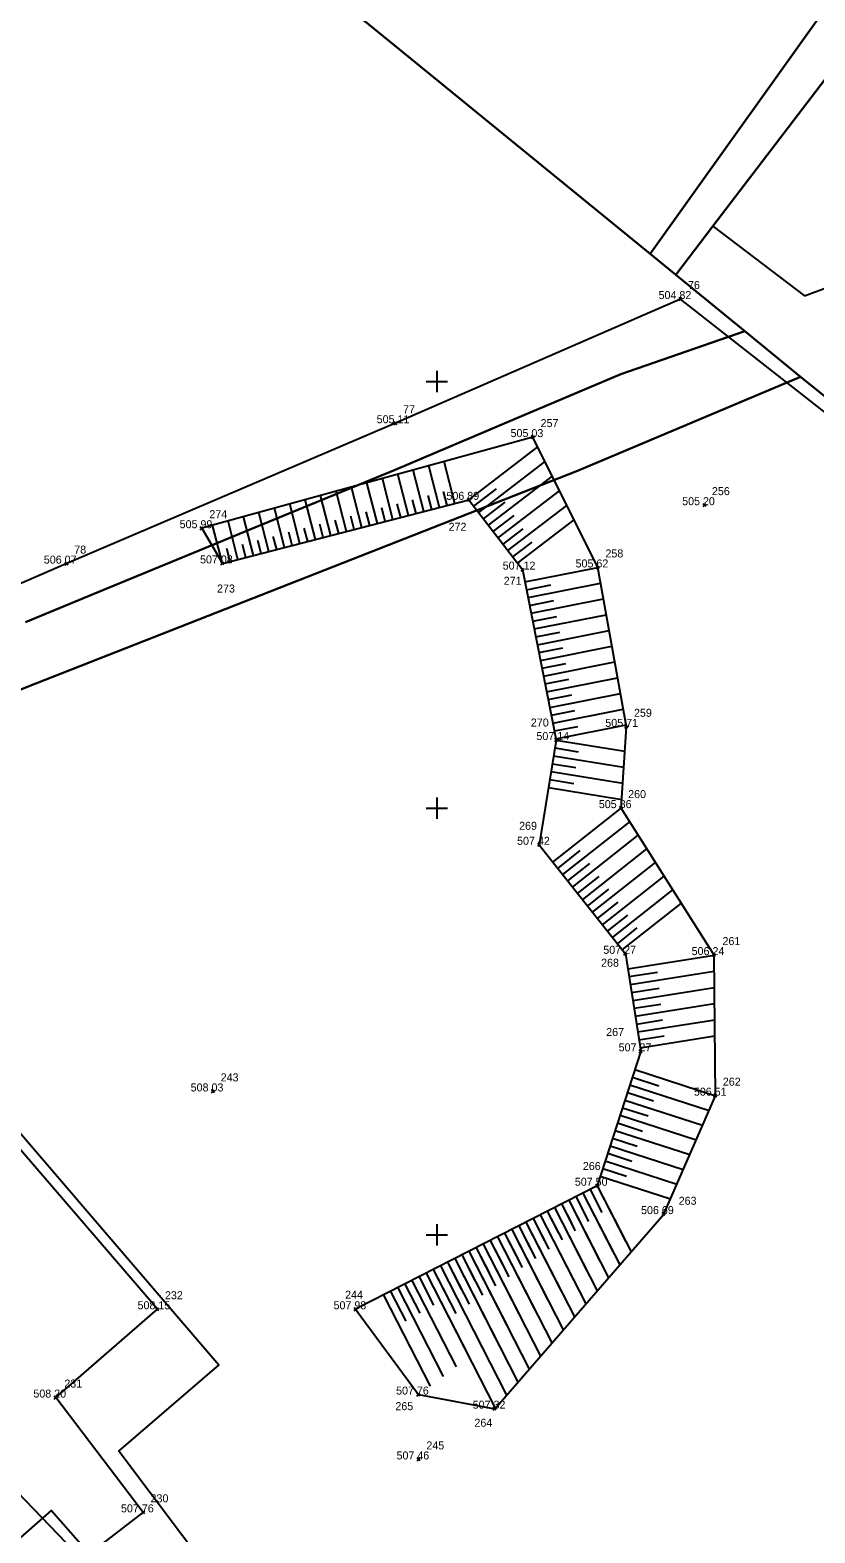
# Model space of a CAD drawing. Extents: x -408550 to -407654, y -1233019 to -1231230.
# Drawn here: x -408039.1 to -408002.3, y -1232014 to -1231943.5 of the extents above; entities that cross this region are included whole.
import ezdxf

# ---------------------------------------------------------------- set-up
doc = ezdxf.new("R2010")
doc.units = 0
for name, color, linetype in [('Level 1', 7, 'Continuous'), ('Level 12', 7, 'Continuous'), ('Level 13', 7, 'Continuous'), ('Level 16', 7, 'Continuous'), ('Level 23', 7, 'Continuous'), ('Level 26', 7, 'Continuous'), ('Level 4', 7, 'Continuous'), ('Level 40', 7, 'Continuous'), ('Level 5', 7, 'Continuous')]:
    doc.layers.add(name, color=color, linetype=linetype)

msp = doc.modelspace()

# ---------------------------------------------------------------- linework, layer by layer
at = {"layer": 'Level 1'}
for p, q in [((-408020, -1231959.5), (-408020, -1231960.5)), ((-408020.5, -1231960), (-408019.5, -1231960)), ((-408020, -1231979.5), (-408020, -1231980.5)), ((-408020.5, -1231980), (-408019.5, -1231980)), ((-408020, -1231999.5), (-408020, -1232000.5)), ((-408020.5, -1232000), (-408019.5, -1232000))]:
    msp.add_line(p, q, dxfattribs=at)
for points in [[(-407991.04, -1231886.54), (-407990.51, -1231886.91), (-407979.53, -1231894.66), (-407981.86, -1231897.95), (-407972.2, -1231905.71), (-407991.32, -1231932.1), (-408007.06, -1231952.72), (-408008.8, -1231955), (-408010, -1231954.02), (-407982.21, -1231915.1), (-407987.32, -1231909.48), (-407982.96, -1231899.31), (-407994.22, -1231890.85)], [(-408000.99, -1231900.39), (-407998.47, -1231896.8), (-407995.49, -1231892.56), (-407994.22, -1231890.85), (-407982.96, -1231899.31), (-407987.32, -1231909.48), (-407982.21, -1231915.1), (-408010, -1231954.02), (-408021.76, -1231944.43), (-408028.78, -1231938.7)], [(-407991.32, -1231932.1), (-407979.12, -1231940.92), (-407973.26, -1231945.16), (-407968, -1231948.96), (-407967.25, -1231949.5), (-407985.37, -1231974.5), (-407998.58, -1231963.3), (-408002.95, -1231959.78), (-408005.56, -1231957.64), (-408008.8, -1231955), (-408007.06, -1231952.72)]]:
    msp.add_lwpolyline(points, close=True, dxfattribs=at)
for points in [[(-408044.57, -1231925.63), (-408028.78, -1231938.7), (-408021.76, -1231944.43), (-408010, -1231954.02), (-408008.8, -1231955), (-408005.56, -1231957.64), (-408011.38, -1231959.66), (-408016.43, -1231961.8), (-408021.95, -1231964.14), (-408028.53, -1231966.85), (-408031.4, -1231968.04), (-408035.38, -1231969.67), (-408039.27, -1231971.28)], [(-408039.27, -1231971.28), (-408035.38, -1231969.67), (-408031.4, -1231968.04), (-408028.53, -1231966.85), (-408021.95, -1231964.14), (-408016.43, -1231961.8), (-408011.38, -1231959.66), (-408005.56, -1231957.64), (-408002.95, -1231959.78), (-408013.4, -1231964.19), (-408038.79, -1231974.16), (-408066.68, -1231985.23)], [(-408066.68, -1231985.23), (-408038.79, -1231974.16), (-408013.4, -1231964.19), (-408002.95, -1231959.78)], [(-408002.95, -1231959.78), (-407998.58, -1231963.3), (-407985.37, -1231974.5), (-407975.08, -1231982.73), (-407972.21, -1231984.54), (-407969.45, -1231986.76), (-407966.11, -1231989.44), (-407955.64, -1231997.88), (-407939.09, -1232011.47), (-407927.08, -1232021.88), (-407908.02, -1232037.31)]]:
    msp.add_lwpolyline(points, dxfattribs=at)
at = {"layer": 'Level 12'}
msp.add_lwpolyline([(-407921.23, -1232026.55), (-407939.09, -1232011.64), (-407955.83, -1231997.88), (-407968.95, -1231986.9), (-407969.06, -1231986.9), (-407974.7, -1231982.55), (-407975.01, -1231982.78), (-407988.1, -1231972.38), (-407997.03, -1231965.19), (-408008.57, -1231956.14), (-408021.93, -1231961.96), (-408037.34, -1231968.54), (-408046.88, -1231972.68)], dxfattribs=at)
at = {"layer": 'Level 13'}
for p, q in [((-408018.49, -1231965.55), (-408015.261, -1231963.071)), ((-408019.147, -1231965.719), (-408019.653, -1231963.755)), ((-408018.033, -1231966.145), (-408014.92, -1231963.755)), ((-408021.325, -1231966.282), (-408021.823, -1231964.352)), ((-408020.599, -1231966.094), (-408021.1, -1231964.153)), ((-408019.873, -1231965.907), (-408020.377, -1231963.954)), ((-408017.577, -1231966.74), (-408014.58, -1231964.439)), ((-408024.23, -1231967.031), (-408024.716, -1231965.148)), ((-408023.504, -1231966.844), (-408023.993, -1231964.949)), ((-408022.778, -1231966.656), (-408023.27, -1231964.75)), ((-408022.052, -1231966.469), (-408022.546, -1231964.551)), ((-408019.51, -1231965.813), (-408019.678, -1231965.161)), ((-408018.262, -1231965.847), (-408017.206, -1231965.037)), ((-408017.12, -1231967.335), (-408014.239, -1231965.124)), ((-408026.409, -1231967.593), (-408026.886, -1231965.745)), ((-408025.683, -1231967.406), (-408026.162, -1231965.546)), ((-408024.956, -1231967.218), (-408025.439, -1231965.347)), ((-408021.688, -1231966.375), (-408021.854, -1231965.735)), ((-408020.962, -1231966.188), (-408021.129, -1231965.544)), ((-408020.236, -1231966), (-408020.403, -1231965.352)), ((-408017.805, -1231966.442), (-408016.788, -1231965.662)), ((-408016.663, -1231967.93), (-408013.899, -1231965.808)), ((-408029.314, -1231968.343), (-408029.779, -1231966.541)), ((-408028.588, -1231968.155), (-408029.055, -1231966.342)), ((-408027.861, -1231967.968), (-408028.332, -1231966.143)), ((-408027.135, -1231967.781), (-408027.609, -1231965.944)), ((-408024.593, -1231967.125), (-408024.755, -1231966.5)), ((-408023.867, -1231966.937), (-408024.029, -1231966.308)), ((-408023.141, -1231966.75), (-408023.304, -1231966.117)), ((-408022.415, -1231966.563), (-408022.579, -1231965.926)), ((-408017.348, -1231967.037), (-408016.37, -1231966.286)), ((-408016.207, -1231968.525), (-408013.559, -1231966.492)), ((-408030.04, -1231968.53), (-408030.502, -1231966.74)), ((-408027.498, -1231967.874), (-408027.656, -1231967.265)), ((-408026.772, -1231967.687), (-408026.93, -1231967.073)), ((-408026.046, -1231967.499), (-408026.205, -1231966.882)), ((-408025.32, -1231967.312), (-408025.48, -1231966.691)), ((-408016.892, -1231967.632), (-408015.952, -1231966.911)), ((-408029.677, -1231968.436), (-408029.831, -1231967.838)), ((-408028.951, -1231968.249), (-408029.106, -1231967.647)), ((-408028.224, -1231968.062), (-408028.381, -1231967.456)), ((-408016.435, -1231968.227), (-408015.534, -1231967.535)), ((-408015.866, -1231969.396), (-408012.45, -1231968.72)), ((-408015.793, -1231969.763), (-408014.658, -1231969.539)), ((-408015.721, -1231970.131), (-408012.318, -1231969.458)), ((-408015.648, -1231970.499), (-408014.517, -1231970.276)), ((-408015.575, -1231970.867), (-408012.185, -1231970.197)), ((-408015.502, -1231971.235), (-408014.376, -1231971.012)), ((-408015.43, -1231971.603), (-408012.053, -1231970.935)), ((-408015.357, -1231971.971), (-408014.235, -1231971.749)), ((-408015.284, -1231972.339), (-408011.92, -1231971.673)), ((-408015.211, -1231972.706), (-408014.093, -1231972.485)), ((-408015.139, -1231973.074), (-408011.788, -1231972.412)), ((-408015.066, -1231973.442), (-408013.952, -1231973.222)), ((-408014.993, -1231973.81), (-408011.655, -1231973.15)), ((-408014.92, -1231974.178), (-408013.811, -1231973.959)), ((-408014.848, -1231974.546), (-408011.523, -1231973.888)), ((-408014.775, -1231974.914), (-408013.67, -1231974.695)), ((-408014.702, -1231975.282), (-408011.39, -1231974.627)), ((-408014.629, -1231975.649), (-408013.529, -1231975.432)), ((-408014.557, -1231976.017), (-408011.258, -1231975.365)), ((-408014.484, -1231976.385), (-408013.388, -1231976.168)), ((-408014.411, -1231976.753), (-408011.126, -1231976.103)), ((-408014.4, -1231976.81), (-408011.185, -1231977.334)), ((-408014.521, -1231977.55), (-408011.234, -1231978.086)), ((-408014.46, -1231977.18), (-408013.378, -1231977.356)), ((-408014.641, -1231978.29), (-408011.284, -1231978.838)), ((-408014.581, -1231977.92), (-408013.475, -1231978.101)), ((-408014.762, -1231979.031), (-408011.333, -1231979.589)), ((-408014.702, -1231978.661), (-408013.572, -1231978.845)), ((-408014.56, -1231982.53), (-408011.36, -1231980)), ((-408014.095, -1231983.118), (-408010.957, -1231980.637)), ((-408013.63, -1231983.706), (-408010.553, -1231981.275)), ((-408014.327, -1231982.824), (-408013.272, -1231981.99)), ((-408013.164, -1231984.295), (-408010.15, -1231981.912)), ((-408013.862, -1231983.412), (-408012.827, -1231982.594)), ((-408012.699, -1231984.883), (-408009.747, -1231982.549)), ((-408013.397, -1231984.001), (-408012.383, -1231983.199)), ((-408012.234, -1231985.471), (-408009.344, -1231983.186)), ((-408012.932, -1231984.589), (-408011.938, -1231983.804)), ((-408011.769, -1231986.06), (-408008.94, -1231983.824)), ((-408012.467, -1231985.177), (-408011.494, -1231984.408)), ((-408011.304, -1231986.648), (-408008.537, -1231984.461)), ((-408012.001, -1231985.766), (-408011.049, -1231985.013)), ((-408011.536, -1231986.354), (-408010.605, -1231985.617)), ((-408011.05, -1231987.528), (-408007, -1231986.89)), ((-408010.992, -1231987.899), (-408009.661, -1231987.689)), ((-408010.933, -1231988.269), (-408006.993, -1231987.648)), ((-408010.817, -1231989.01), (-408006.986, -1231988.406)), ((-408010.875, -1231988.639), (-408009.581, -1231988.436)), ((-408010.758, -1231989.38), (-408009.501, -1231989.182)), ((-408010.7, -1231989.751), (-408006.979, -1231989.164)), ((-408010.641, -1231990.121), (-408009.421, -1231989.929)), ((-408010.583, -1231990.492), (-408006.972, -1231989.923)), ((-408010.525, -1231990.862), (-408009.341, -1231990.675)), ((-408010.466, -1231991.232), (-408006.965, -1231990.681)), ((-408010.833, -1231992.614), (-408009.587, -1231993.017)), ((-408010.717, -1231992.257), (-408006.94, -1231993.48)), ((-408011.064, -1231993.327), (-408009.841, -1231993.723)), ((-408010.948, -1231992.97), (-408007.241, -1231994.171)), ((-408011.295, -1231994.041), (-408010.096, -1231994.429)), ((-408011.18, -1231993.684), (-408007.542, -1231994.862)), ((-408011.526, -1231994.754), (-408010.35, -1231995.135)), ((-408011.411, -1231994.397), (-408007.844, -1231995.552)), ((-408011.757, -1231995.468), (-408010.604, -1231995.841)), ((-408011.642, -1231995.111), (-408008.145, -1231996.243)), ((-408011.988, -1231996.181), (-408010.859, -1231996.547)), ((-408011.873, -1231995.824), (-408008.446, -1231996.934)), ((-408012.104, -1231996.538), (-408008.747, -1231997.625)), ((-408012.335, -1231997.252), (-408009.049, -1231998.316)), ((-408012.219, -1231996.895), (-408011.113, -1231997.253)), ((-408013.482, -1231998.212), (-408012.885, -1231999.378)), ((-408013.482, -1231998.212), (-408013.005, -1231999.144)), ((-408013.148, -1231998.042), (-408011.426, -1232001.409)), ((-408013.148, -1231998.042), (-408011.745, -1232000.784)), ((-408012.814, -1231997.871), (-408012.263, -1231998.947)), ((-408012.814, -1231997.871), (-408012.356, -1231998.766)), ((-408012.48, -1231997.7), (-408010.895, -1232000.798)), ((-408012.48, -1231997.7), (-408011.133, -1232000.334)), ((-408014.817, -1231998.895), (-408014.129, -1232000.24)), ((-408014.817, -1231998.895), (-408014.304, -1231999.899)), ((-408014.483, -1231998.725), (-408012.486, -1232002.629)), ((-408014.483, -1231998.725), (-408012.969, -1232001.685)), ((-408014.149, -1231998.554), (-408013.507, -1231999.809)), ((-408014.149, -1231998.554), (-408013.654, -1231999.522)), ((-408013.815, -1231998.383), (-408011.956, -1232002.019)), ((-408013.815, -1231998.383), (-408012.357, -1232001.235)), ((-408016.152, -1231999.578), (-408015.373, -1232001.103)), ((-408016.152, -1231999.578), (-408015.602, -1232000.655)), ((-408015.819, -1231999.408), (-408013.546, -1232003.85)), ((-408015.819, -1231999.408), (-408014.193, -1232002.586)), ((-408015.485, -1231999.237), (-408014.751, -1232000.672)), ((-408015.485, -1231999.237), (-408014.953, -1232000.277)), ((-408015.151, -1231999.066), (-408013.016, -1232003.24)), ((-408015.151, -1231999.066), (-408013.581, -1232002.135)), ((-408017.488, -1232000.261), (-408016.617, -1232001.965)), ((-408017.488, -1232000.261), (-408016.9, -1232001.41)), ((-408017.154, -1232000.091), (-408014.607, -1232005.071)), ((-408017.154, -1232000.091), (-408015.417, -1232003.486)), ((-408016.82, -1231999.92), (-408015.995, -1232001.534)), ((-408016.82, -1231999.92), (-408016.251, -1232001.033)), ((-408016.486, -1231999.749), (-408014.076, -1232004.461)), ((-408016.486, -1231999.749), (-408014.805, -1232003.036)), ((-408018.823, -1232000.945), (-408017.861, -1232002.827)), ((-408018.823, -1232000.945), (-408018.199, -1232002.166)), ((-408018.49, -1232000.774), (-408015.667, -1232006.292)), ((-408018.49, -1232000.774), (-408016.642, -1232004.387)), ((-408018.156, -1232000.603), (-408017.239, -1232002.396)), ((-408018.156, -1232000.603), (-408017.55, -1232001.788)), ((-408017.822, -1232000.432), (-408015.137, -1232005.682)), ((-408017.822, -1232000.432), (-408016.029, -1232003.936)), ((-408020.493, -1232001.798), (-408017.257, -1232008.124)), ((-408020.493, -1232001.798), (-408018.478, -1232005.738)), ((-408020.159, -1232001.628), (-408019.104, -1232003.689)), ((-408020.159, -1232001.628), (-408019.497, -1232002.921)), ((-408019.825, -1232001.457), (-408016.727, -1232007.513)), ((-408019.825, -1232001.457), (-408017.866, -1232005.287)), ((-408019.491, -1232001.286), (-408018.482, -1232003.258)), ((-408019.491, -1232001.286), (-408018.848, -1232002.544)), ((-408019.157, -1232001.115), (-408016.197, -1232006.903)), ((-408019.157, -1232001.115), (-408017.254, -1232004.837)), ((-408021.828, -1232002.481), (-408019.702, -1232006.638)), ((-408021.494, -1232002.311), (-408020.796, -1232003.677)), ((-408021.16, -1232002.14), (-408019.09, -1232006.188)), ((-408020.827, -1232001.969), (-408020.146, -1232003.299)), ((-408022.496, -1232002.823), (-408020.314, -1232007.088)), ((-408022.162, -1232002.652), (-408021.445, -1232004.054))]:
    msp.add_line(p, q, dxfattribs=at)
msp.add_lwpolyline([(-408031.01, -1231966.88), (-408030.04, -1231968.53), (-408018.49, -1231965.55), (-408015.98, -1231968.82), (-408014.4, -1231976.81), (-408015.2, -1231981.72), (-408011.16, -1231986.83), (-408010.44, -1231991.4), (-408012.48, -1231997.7), (-408023.8, -1232003.49), (-408020.86, -1232007.49), (-408017.28, -1232008.15), (-408009.36, -1231999.03), (-408006.94, -1231993.48), (-408007, -1231986.89), (-408011.36, -1231980), (-408011.11, -1231976.19), (-408012.45, -1231968.72), (-408015.49, -1231962.61)], close=True, dxfattribs=at)
at = {"layer": 'Level 16'}
msp.add_lwpolyline([(-408049.58, -1232017.9), (-408041.2, -1232010.45), (-408036.62, -1232015.22), (-408033.75, -1232013.01), (-408037.85, -1232007.63), (-408033.09, -1232003.49), (-408050.82, -1231982.86), (-408065.24, -1231994.98), (-408068.9, -1231990.83), (-408072.14, -1231993.67), (-408068.54, -1231997.8)], close=True, dxfattribs=at)
at = {"layer": 'Level 23'}
for points in [[(-408008.501, -1231956.209), (-408008.639, -1231956.071)], [(-408008.639, -1231956.209), (-408008.501, -1231956.071)], [(-408021.861, -1231962.029), (-408021.999, -1231961.891)], [(-408021.999, -1231962.029), (-408021.861, -1231961.891)], [(-408015.421, -1231962.679), (-408015.559, -1231962.541)], [(-408015.559, -1231962.679), (-408015.421, -1231962.541)], [(-408018.421, -1231965.619), (-408018.559, -1231965.481)], [(-408018.559, -1231965.619), (-408018.421, -1231965.481)], [(-408007.381, -1231965.869), (-408007.519, -1231965.731)], [(-408007.519, -1231965.869), (-408007.381, -1231965.731)], [(-408030.941, -1231966.949), (-408031.079, -1231966.811)], [(-408031.079, -1231966.949), (-408030.941, -1231966.811)], [(-408037.271, -1231968.609), (-408037.409, -1231968.471)], [(-408037.409, -1231968.609), (-408037.271, -1231968.471)], [(-408029.971, -1231968.599), (-408030.109, -1231968.461)], [(-408030.109, -1231968.599), (-408029.971, -1231968.461)], [(-408012.381, -1231968.789), (-408012.519, -1231968.651)], [(-408012.519, -1231968.789), (-408012.381, -1231968.651)], [(-408015.911, -1231968.889), (-408016.049, -1231968.751)], [(-408016.049, -1231968.889), (-408015.911, -1231968.751)], [(-408011.041, -1231976.259), (-408011.179, -1231976.121)], [(-408011.179, -1231976.259), (-408011.041, -1231976.121)], [(-408014.331, -1231976.879), (-408014.469, -1231976.741)], [(-408014.469, -1231976.879), (-408014.331, -1231976.741)], [(-408011.291, -1231980.069), (-408011.429, -1231979.931)], [(-408011.429, -1231980.069), (-408011.291, -1231979.931)], [(-408015.131, -1231981.789), (-408015.269, -1231981.651)], [(-408015.269, -1231981.789), (-408015.131, -1231981.651)], [(-408011.091, -1231986.899), (-408011.229, -1231986.761)], [(-408011.229, -1231986.899), (-408011.091, -1231986.761)], [(-408006.931, -1231986.959), (-408007.069, -1231986.821)], [(-408007.069, -1231986.959), (-408006.931, -1231986.821)], [(-408010.371, -1231991.469), (-408010.509, -1231991.331)], [(-408010.509, -1231991.469), (-408010.371, -1231991.331)], [(-408030.411, -1231993.349), (-408030.549, -1231993.211)], [(-408030.549, -1231993.349), (-408030.411, -1231993.211)], [(-408006.871, -1231993.549), (-408007.009, -1231993.411)], [(-408007.009, -1231993.549), (-408006.871, -1231993.411)], [(-408012.411, -1231997.769), (-408012.549, -1231997.631)], [(-408012.549, -1231997.769), (-408012.411, -1231997.631)], [(-408009.291, -1231999.099), (-408009.429, -1231998.961)], [(-408009.429, -1231999.099), (-408009.291, -1231998.961)], [(-408033.021, -1232003.559), (-408033.159, -1232003.421)], [(-408033.159, -1232003.559), (-408033.021, -1232003.421)], [(-408023.731, -1232003.559), (-408023.869, -1232003.421)], [(-408023.869, -1232003.559), (-408023.731, -1232003.421)], [(-408020.791, -1232007.559), (-408020.929, -1232007.421)], [(-408020.929, -1232007.559), (-408020.791, -1232007.421)], [(-408037.781, -1232007.699), (-408037.919, -1232007.561)], [(-408037.919, -1232007.699), (-408037.781, -1232007.561)], [(-408017.211, -1232008.219), (-408017.349, -1232008.081)], [(-408017.349, -1232008.219), (-408017.211, -1232008.081)], [(-408020.771, -1232010.599), (-408020.909, -1232010.461)], [(-408020.909, -1232010.599), (-408020.771, -1232010.461)], [(-408033.681, -1232013.079), (-408033.819, -1232012.941)], [(-408033.819, -1232013.079), (-408033.681, -1232012.941)]]:
    msp.add_lwpolyline(points, dxfattribs=at)
at = {"layer": 'Level 4'}
msp.add_lwpolyline([(-408066.68, -1231985.23), (-408038.79, -1231974.16), (-408013.4, -1231964.19), (-408002.95, -1231959.78), (-408005.56, -1231957.64), (-408008.8, -1231955), (-408010, -1231954.02), (-408021.76, -1231944.43), (-408028.78, -1231938.7), (-408044.57, -1231925.63)], dxfattribs=at)
at = {"layer": 'Level 5'}
for p, q in [((-408002.77, -1231955.98), (-407973.26, -1231945.16)), ((-408007.06, -1231952.72), (-408002.77, -1231955.98))]:
    msp.add_line(p, q, dxfattribs=at)
msp.add_lwpolyline([(-408065.17, -1231999.95), (-408047.88, -1231985.48), (-408030.21, -1232006.09), (-408034.89, -1232010.12), (-408030.45, -1232016.04), (-408033.3, -1232018.35), (-408038.07, -1232012.92), (-408046.69, -1232020.5)], dxfattribs=at)

# ---------------------------------------------------------------- texts
at = {"layer": 'Level 26'}
for s, p in [('76', (-408008.226, -1231955.67)), ('77', (-408021.576, -1231961.49)), ('257', (-408015.134, -1231962.14)), ('256', (-408007.104, -1231965.33)), ('274', (-408030.654, -1231966.41)), ('272', (-408019.444, -1231967)), ('78', (-408036.986, -1231968.07)), ('258', (-408012.094, -1231968.25)), ('271', (-408016.86, -1231969.532)), ('273', (-408030.292, -1231969.894)), ('259', (-408010.755, -1231975.72)), ('270', (-408015.588, -1231976.176)), ('260', (-408011.03, -1231979.53)), ('269', (-408016.139, -1231981.016)), ('261', (-408006.61, -1231986.42)), ('268', (-408012.298, -1231987.434)), ('267', (-408012.058, -1231990.683)), ('243', (-408030.124, -1231992.81)), ('262', (-408006.594, -1231993.01)), ('266', (-408013.153, -1231996.964)), ('263', (-408008.662, -1231998.592)), ('232', (-408032.734, -1232003.02)), ('244', (-408024.292, -1232002.993)), ('231', (-408037.449, -1232007.16)), ('265', (-408021.937, -1232008.22)), ('264', (-408018.233, -1232008.997)), ('245', (-408020.484, -1232010.06)), ('230', (-408033.41, -1232012.54))]:
    msp.add_text(s, height=0.375, dxfattribs=at).set_placement(p)
at = {"layer": 'Level 40'}
for s, p in [('504 82', (-408009.604, -1231956.14)), ('505 11', (-408022.813, -1231961.96)), ('505 03', (-408016.54, -1231962.61)), ('506 89', (-408019.546, -1231965.55)), ('505 20', (-408008.5, -1231965.8)), ('505 99', (-408032.047, -1231966.88)), ('506 07', (-408038.411, -1231968.54)), ('507 08', (-408031.09, -1231968.53)), ('507 12', (-408016.908, -1231968.82)), ('505 62', (-408013.494, -1231968.72)), ('507 14', (-408015.328, -1231976.81)), ('505 71', (-408012.1, -1231976.19)), ('505 86', (-408012.404, -1231980)), ('507 42', (-408016.234, -1231981.72)), ('507 27', (-408012.194, -1231986.83)), ('506 24', (-408008.055, -1231986.89)), ('507 27', (-408011.474, -1231991.4)), ('508 03', (-408031.53, -1231993.28)), ('506 51', (-408007.95, -1231993.48)), ('507 50', (-408013.53, -1231997.7)), ('506 69', (-408010.426, -1231999.03)), ('508 15', (-408034.018, -1232003.49)), ('507 98', (-408024.835, -1232003.49)), ('508 20', (-408038.9, -1232007.63)), ('507 76', (-408021.904, -1232007.49)), ('507 32', (-408018.314, -1232008.15)), ('507 46', (-408021.884, -1232010.53)), ('507 76', (-408034.794, -1232013.01))]:
    msp.add_text(s, height=0.375, dxfattribs=at).set_placement(p)

doc.saveas('drawing.dxf')
